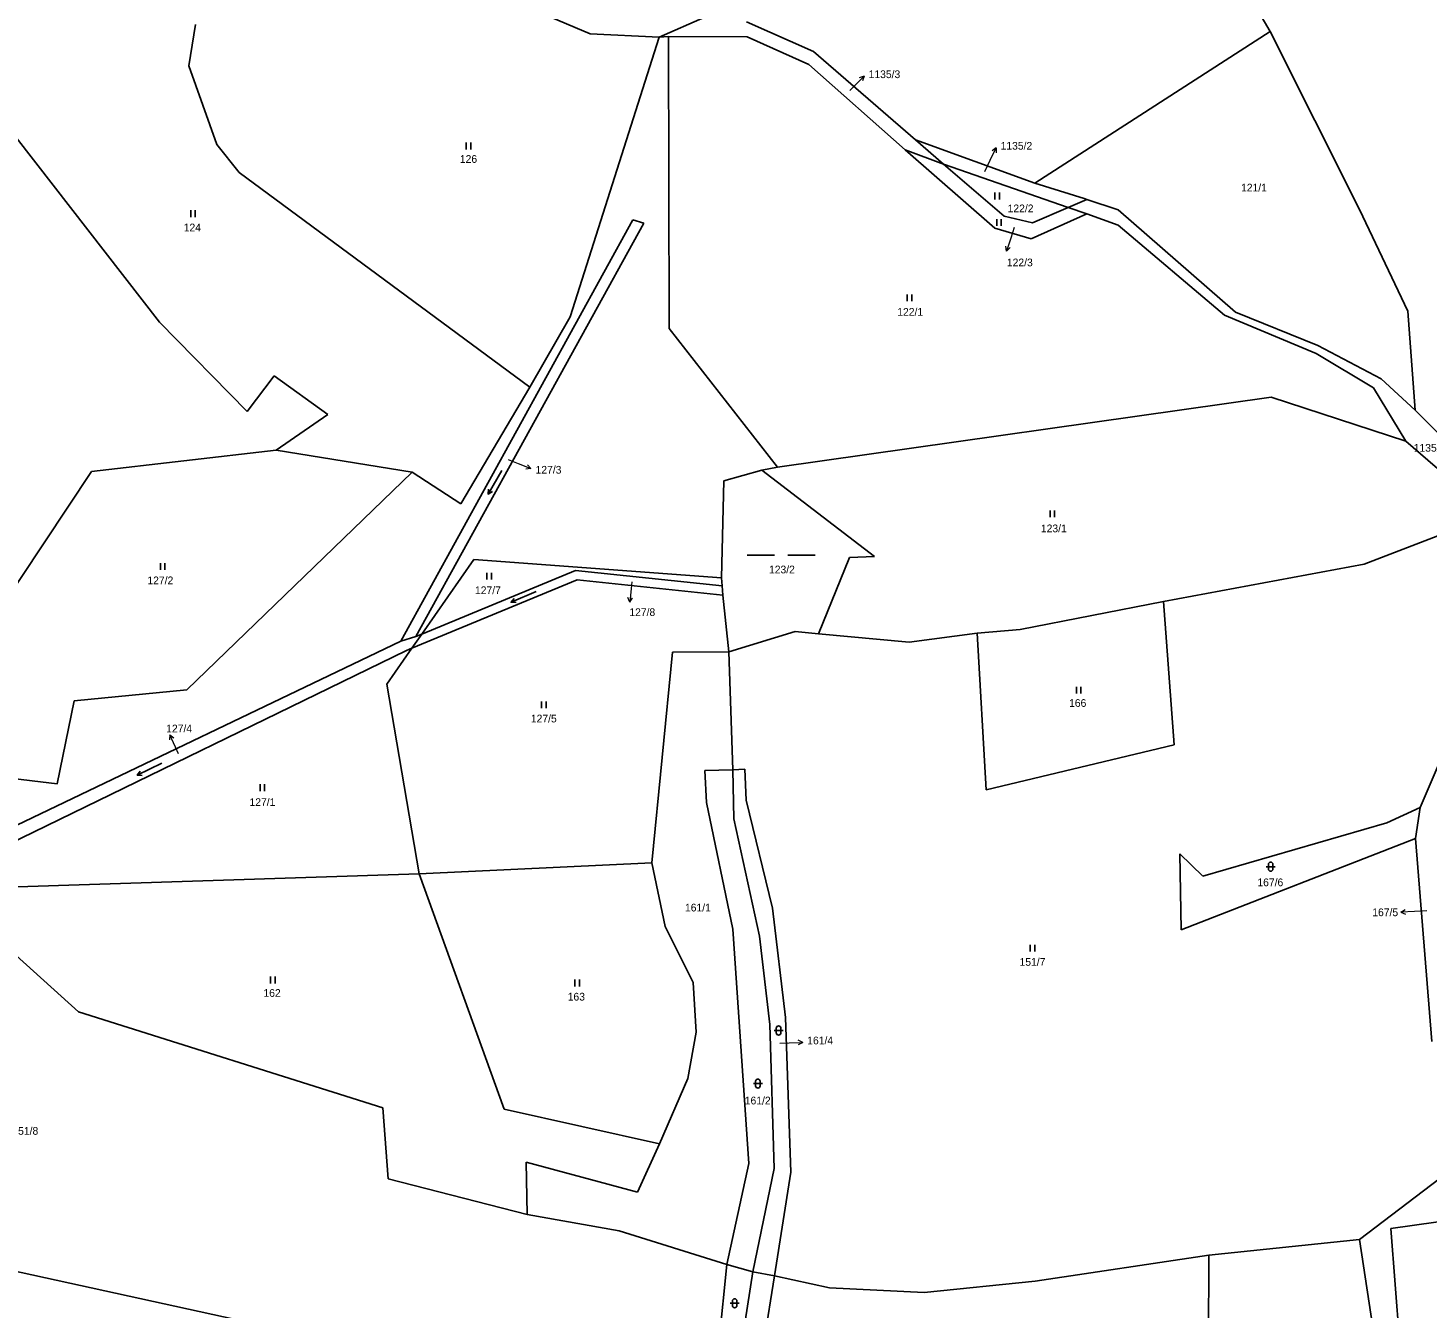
# Model space of a CAD drawing. Extents: x -765428 to -762163, y -1107632 to -1104975.
# Drawn here: x -763576.9 to -763268.9, y -1106368.4 to -1106086.6 of the extents above; entities that cross this region are included whole.
import ezdxf
from ezdxf.enums import TextEntityAlignment as Align

# ---------------------------------------------------------------- set-up
doc = ezdxf.new("R2010")
doc.units = 0
doc.header["$LTSCALE"] = 0.68
for name, color, linetype, lineweight in [('1', 7, 'Continuous', 25), ('3', 7, 'Continuous', 25), ('7', 7, 'Continuous', 13)]:
    doc.layers.add(name, color=color, linetype=linetype, lineweight=lineweight)
doc.layers.add('2', color=7, linetype='Continuous')

msp = doc.modelspace()

# ---------------------------------------------------------------- linework, layer by layer
at = {"layer": '1'}
for p, q in [((-763329.35, -1106043.44), (-763303.61, -1106087.39)), ((-763453.2, -1106087.94), (-763472.16, -1106079.89)), ((-763541.52, -1106094.99), (-763540.04, -1106085.9)), ((-763428.02, -1106084.29), (-763438.04, -1106088.64)), ((-763404.09, -1106091.81), (-763418.79, -1106085.26)), ((-763457.64, -1106150.19), (-763438.04, -1106088.64)), ((-763438.04, -1106088.64), (-763453.2, -1106087.94)), ((-763435.94, -1106088.55), (-763438.04, -1106088.64)), ((-763435.8, -1106152.77), (-763435.94, -1106088.55)), ((-763418.65, -1106088.59), (-763435.94, -1106088.55)), ((-763405.1, -1106094.66), (-763418.65, -1106088.59)), ((-763303.61, -1106087.39), (-763355.41, -1106120.75)), ((-763303.61, -1106087.39), (-763284, -1106126.56)), ((-763381.62, -1106111.27), (-763404.09, -1106091.81)), ((-763535.34, -1106112.24), (-763541.52, -1106094.99)), ((-763383.95, -1106113.42), (-763405.1, -1106094.66)), ((-763583.36, -1106105.79), (-763547.96, -1106151.37)), ((-763381.62, -1106111.27), (-763375.48, -1106116.58)), ((-763355.41, -1106120.75), (-763381.62, -1106111.27)), ((-763530.4, -1106118.46), (-763535.34, -1106112.24)), ((-763375.48, -1106116.58), (-763383.95, -1106113.42)), ((-763383.95, -1106113.42), (-763364.21, -1106130.66)), ((-763375.48, -1106116.58), (-763362.16, -1106128)), ((-763348.04, -1106126.1), (-763375.48, -1106116.58)), ((-763466.45, -1106165.63), (-763530.4, -1106118.46)), ((-763344.52, -1106124.15), (-763355.41, -1106120.75)), ((-763355.89, -1106129.48), (-763348.04, -1106126.1)), ((-763348.04, -1106126.1), (-763343.95, -1106124.34)), ((-763343.96, -1106127.52), (-763348.04, -1106126.1)), ((-763343.95, -1106124.34), (-763344.52, -1106124.15)), ((-763337.08, -1106126.66), (-763343.95, -1106124.34)), ((-763311.25, -1106149.14), (-763337.08, -1106126.66)), ((-763284, -1106126.56), (-763273.31, -1106148.94)), ((-763443.8, -1106128.85), (-763494.88, -1106221.53)), ((-763441.41, -1106129.57), (-763491.52, -1106220.5)), ((-763443.8, -1106128.85), (-763441.41, -1106129.57)), ((-763362.16, -1106128), (-763355.89, -1106129.48)), ((-763356.22, -1106132.99), (-763343.96, -1106127.52)), ((-763337.06, -1106130), (-763343.96, -1106127.52)), ((-763313.65, -1106149.79), (-763337.06, -1106130)), ((-763364.21, -1106130.66), (-763356.22, -1106132.99)), ((-763547.96, -1106151.37), (-763528.69, -1106170.98)), ((-763466.45, -1106165.63), (-763457.64, -1106150.19)), ((-763293.51, -1106158.23), (-763313.65, -1106149.79)), ((-763293.11, -1106156.45), (-763311.25, -1106149.14)), ((-763273.31, -1106148.94), (-763271.76, -1106170.68)), ((-763435.8, -1106152.77), (-763412.03, -1106183.24)), ((-763279.18, -1106163.78), (-763293.11, -1106156.45)), ((-763280.88, -1106165.81), (-763293.51, -1106158.23)), ((-763528.69, -1106170.98), (-763522.7, -1106163.17)), ((-763522.7, -1106163.17), (-763510.94, -1106171.64)), ((-763271.76, -1106170.68), (-763279.18, -1106163.78)), ((-763481.66, -1106191.32), (-763466.45, -1106165.63)), ((-763273.81, -1106177.51), (-763280.88, -1106165.81)), ((-763303.4, -1106167.85), (-763412.03, -1106183.24)), ((-763273.81, -1106177.51), (-763303.4, -1106167.85)), ((-763510.94, -1106171.64), (-763522.29, -1106179.5)), ((-763257.11, -1106185.37), (-763271.76, -1106170.68)), ((-763255.03, -1106193.78), (-763273.81, -1106177.51)), ((-763522.29, -1106179.5), (-763562.87, -1106184.23)), ((-763522.29, -1106179.5), (-763492.36, -1106184.33)), ((-763562.87, -1106184.23), (-763591.84, -1106227.65)), ((-763541.93, -1106232.24), (-763492.36, -1106184.33)), ((-763492.36, -1106184.33), (-763481.66, -1106191.32)), ((-763415.47, -1106183.87), (-763423.77, -1106186.22)), ((-763412.03, -1106183.24), (-763415.47, -1106183.87)), ((-763390.67, -1106202.88), (-763415.47, -1106183.87)), ((-763423.77, -1106186.22), (-763424.35, -1106207.55)), ((-763282.95, -1106204.58), (-763256.59, -1106194.39)), ((-763490.23, -1106219.97), (-763478.79, -1106203.58)), ((-763478.79, -1106203.58), (-763424.35, -1106207.55)), ((-763396.19, -1106203.09), (-763402.95, -1106219.87)), ((-763390.67, -1106202.88), (-763396.19, -1106203.09)), ((-763456.42, -1106205.99), (-763490.23, -1106219.97)), ((-763456.42, -1106205.99), (-763424.17, -1106209.36)), ((-763327.09, -1106212.77), (-763282.95, -1106204.58)), ((-763456.05, -1106208.06), (-763492.41, -1106223.08)), ((-763456.05, -1106208.06), (-763424, -1106211.41)), ((-763424.35, -1106207.55), (-763424.17, -1106209.36)), ((-763424.17, -1106209.36), (-763424, -1106211.41)), ((-763424, -1106211.41), (-763422.67, -1106223.88)), ((-763358.6, -1106218.92), (-763327.09, -1106212.77)), ((-763324.71, -1106244.32), (-763327.09, -1106212.77)), ((-763408.12, -1106219.4), (-763422.67, -1106223.88)), ((-763402.95, -1106219.87), (-763408.12, -1106219.4)), ((-763368.08, -1106219.78), (-763358.6, -1106218.92)), ((-763494.88, -1106221.53), (-763581.17, -1106262.89)), ((-763491.52, -1106220.5), (-763494.88, -1106221.53)), ((-763492.41, -1106223.08), (-763490.23, -1106219.97)), ((-763490.23, -1106219.97), (-763491.52, -1106220.5)), ((-763402.95, -1106219.87), (-763383.06, -1106221.73)), ((-763383.06, -1106221.73), (-763368.08, -1106219.78)), ((-763368.08, -1106219.78), (-763366.08, -1106254.19)), ((-763493.63, -1106223.59), (-763581.23, -1106266.21)), ((-763497.9, -1106230.95), (-763492.41, -1106223.08)), ((-763492.41, -1106223.08), (-763493.63, -1106223.59)), ((-763439.61, -1106270.25), (-763435.09, -1106223.93)), ((-763435.09, -1106223.93), (-763422.67, -1106223.88)), ((-763421.84, -1106249.8), (-763422.67, -1106223.88)), ((-763490.85, -1106272.72), (-763497.9, -1106230.95)), ((-763566.7, -1106234.64), (-763541.93, -1106232.24)), ((-763366.08, -1106254.19), (-763324.71, -1106244.32)), ((-763427.96, -1106249.98), (-763421.84, -1106249.8)), ((-763427.64, -1106256.97), (-763427.96, -1106249.98)), ((-763421.84, -1106249.8), (-763419.19, -1106249.66)), ((-763421.84, -1106249.8), (-763421.57, -1106260.61)), ((-763419.19, -1106249.66), (-763418.86, -1106256.49)), ((-763270.65, -1106258.08), (-763265.98, -1106247.33)), ((-763421.84, -1106284.89), (-763427.64, -1106256.97)), ((-763418.86, -1106256.49), (-763413.11, -1106280.26)), ((-763277.95, -1106261.45), (-763270.65, -1106258.08)), ((-763270.65, -1106258.08), (-763271.65, -1106264.9)), ((-763421.57, -1106260.61), (-763415.98, -1106286.39)), ((-763318.47, -1106273.2), (-763277.95, -1106261.45)), ((-763323.22, -1106285.03), (-763271.65, -1106264.9)), ((-763271.65, -1106264.9), (-763268.06, -1106309.55)), ((-763323.47, -1106268.29), (-763318.47, -1106273.2)), ((-763323.47, -1106268.29), (-763323.22, -1106285.03)), ((-763490.85, -1106272.72), (-763439.61, -1106270.25)), ((-763436.68, -1106284.24), (-763439.61, -1106270.25)), ((-763599.23, -1106276.16), (-763490.85, -1106272.72)), ((-763490.85, -1106272.72), (-763472.1, -1106324.42)), ((-763413.11, -1106280.26), (-763410.26, -1106304.3)), ((-763430.55, -1106296.62), (-763436.68, -1106284.24)), ((-763418.28, -1106336.44), (-763421.84, -1106284.89)), ((-763415.98, -1106286.39), (-763413.7, -1106305.8)), ((-763565.74, -1106303.01), (-763579.48, -1106290.69)), ((-763429.89, -1106307.5), (-763430.55, -1106296.62)), ((-763498.83, -1106324.16), (-763565.74, -1106303.01)), ((-763410.26, -1106304.3), (-763409.07, -1106338.32)), ((-763431.74, -1106317.74), (-763429.89, -1106307.5)), ((-763413.7, -1106305.8), (-763412.73, -1106337.54)), ((-763437.94, -1106332.06), (-763431.74, -1106317.74)), ((-763497.64, -1106339.78), (-763498.83, -1106324.16)), ((-763472.1, -1106324.42), (-763437.94, -1106332.06)), ((-763442.76, -1106342.69), (-763437.94, -1106332.06)), ((-763467.25, -1106336.14), (-763442.76, -1106342.69)), ((-763467.25, -1106336.14), (-763467.04, -1106347.59)), ((-763423.16, -1106358.59), (-763418.28, -1106336.44)), ((-763412.73, -1106337.54), (-763417.41, -1106360.22)), ((-763409.07, -1106338.32), (-763412.69, -1106361.14)), ((-763262.82, -1106337.09), (-763283.96, -1106353.12)), ((-763467.04, -1106347.59), (-763497.64, -1106339.78)), ((-763467.04, -1106347.59), (-763446.83, -1106351.23)), ((-763251.8, -1106347.17), (-763277.09, -1106350.73)), ((-763618.27, -1106351.7), (-763461.07, -1106385.99)), ((-763446.83, -1106351.23), (-763423.16, -1106358.59)), ((-763277.09, -1106350.73), (-763273.44, -1106397.91)), ((-763283.96, -1106353.12), (-763317.15, -1106356.55)), ((-763283.96, -1106353.12), (-763277.16, -1106397.91)), ((-763355.33, -1106362.27), (-763317.15, -1106356.55)), ((-763317.15, -1106356.55), (-763317.25, -1106398.34)), ((-763427.18, -1106398.62), (-763423.16, -1106358.59)), ((-763417.41, -1106360.22), (-763423.99, -1106401.96)), ((-763417.41, -1106360.22), (-763423.16, -1106358.59)), ((-763412.69, -1106361.14), (-763419.03, -1106401.1)), ((-763417.41, -1106360.22), (-763412.69, -1106361.14)), ((-763412.69, -1106361.14), (-763400.59, -1106363.72)), ((-763400.59, -1106363.72), (-763379.74, -1106364.79)), ((-763379.74, -1106364.79), (-763355.33, -1106362.27))]:
    msp.add_line(p, q, dxfattribs=at)
msp.add_lwpolyline([(-763593.73, -1106250.12), (-763570.42, -1106252.88), (-763566.7, -1106234.64)], dxfattribs=at)
at = {"layer": '3'}
for p, q in [((-763480.491, -1106113.34), (-763480.491, -1106111.84)), ((-763479.49, -1106113.34), (-763479.49, -1106111.84)), ((-763364.201, -1106124.36), (-763364.201, -1106122.86)), ((-763363.2, -1106124.36), (-763363.2, -1106122.86)), ((-763541.071, -1106128.23), (-763541.071, -1106126.73)), ((-763540.07, -1106128.23), (-763540.07, -1106126.73)), ((-763363.781, -1106130.18), (-763363.781, -1106128.68)), ((-763362.78, -1106130.18), (-763362.78, -1106128.68)), ((-763383.461, -1106146.75), (-763383.461, -1106145.25)), ((-763382.46, -1106146.75), (-763382.46, -1106145.25)), ((-763475.646, -1106189.159), (-763475.592, -1106188.062)), ((-763352.041, -1106194.24), (-763352.041, -1106192.74)), ((-763351.04, -1106194.24), (-763351.04, -1106192.74)), ((-763418.689, -1106202.63), (-763412.689, -1106202.63)), ((-763409.689, -1106202.63), (-763403.689, -1106202.63)), ((-763547.751, -1106205.85), (-763547.751, -1106204.35)), ((-763546.75, -1106205.85), (-763546.75, -1106204.35)), ((-763475.911, -1106207.95), (-763475.911, -1106206.45)), ((-763474.91, -1106207.95), (-763474.91, -1106206.45)), ((-763470.601, -1106212.941), (-763469.897, -1106212.098)), ((-763346.261, -1106233.05), (-763346.261, -1106231.55)), ((-763345.26, -1106233.05), (-763345.26, -1106231.55)), ((-763463.921, -1106236.26), (-763463.921, -1106234.76)), ((-763462.92, -1106236.26), (-763462.92, -1106234.76)), ((-763552.856, -1106251.005), (-763552.197, -1106250.126)), ((-763525.811, -1106254.5), (-763525.811, -1106253)), ((-763524.81, -1106254.5), (-763524.81, -1106253)), ((-763304.511, -1106271.121), (-763302.509, -1106271.121)), ((-763304.011, -1106270.621), (-763304.011, -1106271.622)), ((-763303.009, -1106271.622), (-763303.009, -1106270.621)), ((-763356.421, -1106289.79), (-763356.421, -1106288.29)), ((-763355.42, -1106289.79), (-763355.42, -1106288.29)), ((-763523.521, -1106296.8), (-763523.521, -1106295.3)), ((-763522.52, -1106296.8), (-763522.52, -1106295.3)), ((-763456.591, -1106297.44), (-763456.591, -1106295.94)), ((-763455.59, -1106297.44), (-763455.59, -1106295.94)), ((-763412.761, -1106307.151), (-763410.759, -1106307.151)), ((-763412.261, -1106306.651), (-763412.261, -1106307.652)), ((-763411.259, -1106307.652), (-763411.259, -1106306.651)), ((-763417.311, -1106318.831), (-763415.309, -1106318.831)), ((-763416.811, -1106318.331), (-763416.811, -1106319.332)), ((-763415.809, -1106319.332), (-763415.809, -1106318.331)), ((-763422.431, -1106367.141), (-763420.429, -1106367.141)), ((-763421.931, -1106366.641), (-763421.931, -1106367.642)), ((-763420.929, -1106367.642), (-763420.929, -1106366.641))]:
    msp.add_line(p, q, dxfattribs=at)
for points in [[(-763472.646, -1106183.962), (-763475.646, -1106189.159), (-763474.723, -1106188.563)], [(-763465.078, -1106210.597), (-763470.601, -1106212.941), (-763469.505, -1106213.021)], [(-763547.463, -1106248.375), (-763552.856, -1106251.005), (-763551.757, -1106251.027)]]:
    msp.add_lwpolyline(points, dxfattribs=at)
for centre, start, end in [((-763303.51, -1106270.6209), 0, 180), ((-763303.51, -1106271.6209), 180, 359.98789), ((-763411.76, -1106306.6509), 0, 180), ((-763411.76, -1106307.6509), 180, 359.98789), ((-763416.31, -1106318.3309), 0, 180), ((-763416.31, -1106319.3309), 180, 359.98789), ((-763421.43, -1106366.6409), 0, 180), ((-763421.43, -1106367.6409), 180, 359.98789)]:
    msp.add_arc(centre, 0.5, start, end, dxfattribs=at)
at = {"layer": '7'}
for p, q in [((-763392.948, -1106097.238), (-763394.01, -1106097.592)), ((-763363.932, -1106112.97), (-763364.809, -1106113.666)), ((-763361.597, -1106135.714), (-763360.812, -1106134.916)), ((-763466.248, -1106183.564), (-763466.988, -1106182.725)), ((-763444.504, -1106212.935), (-763443.901, -1106211.991)), ((-763545.688, -1106242.09), (-763545.719, -1106243.209)), ((-763274.907, -1106281.117), (-763273.881, -1106281.565)), ((-763406.461, -1106309.755), (-763407.479, -1106309.29))]:
    msp.add_line(p, q, dxfattribs=at)
for points in [[(-763396.1, -1106100.38), (-763395.07, -1106099.36), (-763392.948, -1106097.238), (-763393.302, -1106098.3)], [(-763366.39, -1106118.21), (-763365.2, -1106115.69), (-763363.932, -1106112.97), (-763363.901, -1106114.089)], [(-763359.91, -1106130.55), (-763360.67, -1106132.86), (-763361.597, -1106135.714), (-763361.764, -1106134.607)], [(-763471.25, -1106181.53), (-763469.03, -1106182.44), (-763466.248, -1106183.564), (-763467.364, -1106183.653)], [(-763444.04, -1106208.46), (-763444.19, -1106209.95), (-763444.504, -1106212.935), (-763444.897, -1106211.886)], [(-763543.74, -1106246.29), (-763544.42, -1106244.81), (-763545.688, -1106242.09), (-763544.811, -1106242.786)], [(-763269.15, -1106280.81), (-763271.91, -1106280.96), (-763274.907, -1106281.117), (-763273.933, -1106280.565)], [(-763411.52, -1106309.92), (-763409.46, -1106309.86), (-763406.461, -1106309.755), (-763407.444, -1106310.291)]]:
    msp.add_lwpolyline(points, dxfattribs=at)

# ---------------------------------------------------------------- texts
at = {"layer": '2'}
for s, p in [('1135/3', (-763391.95, -1106097.665)), ('1135/2', (-763362.92, -1106113.405)), ('126', (-763481.87, -1106116.305)), ('121/1', (-763310.03, -1106122.605)), ('127/3', (-763465.22, -1106184.665)), ('123/1', (-763354.06, -1106197.565)), ('123/2', (-763413.87, -1106206.605)), ('167/6', (-763306.43, -1106275.415)), ('161/1', (-763432.35, -1106280.965)), ('161/4', (-763405.46, -1106310.195))]:
    msp.add_text(s, height=1.7, dxfattribs=at).set_placement(p)
for s, p in [('122/2', (-763358.53, -1106127.175)), ('124', (-763540.719, -1106131.375)), ('122/1', (-763382.81, -1106149.945)), ('1135/1', (-763268.57, -1106179.835)), ('127/2', (-763547.76, -1106208.995)), ('127/7', (-763475.7, -1106211.175)), ('166', (-763345.959, -1106235.965)), ('127/5', (-763463.41, -1106239.385)), ('127/1', (-763525.3, -1106257.765)), ('151/7', (-763355.91, -1106292.915)), ('162', (-763523.179, -1106299.745)), ('163', (-763456.249, -1106300.565)), ('161/2', (-763416.35, -1106323.405)), ('151/8', (-763577.46, -1106330.085))]:
    msp.add_text(s, height=1.7, dxfattribs=at).set_placement(p, align=Align.CENTER)
for s, p in [('122/3', (-763355.85, -1106139.065)), ('127/8', (-763438.9, -1106215.985)), ('127/4', (-763540.78, -1106241.575)), ('167/5', (-763275.47, -1106282.005))]:
    msp.add_text(s, height=1.7, dxfattribs=at).set_placement(p, align=Align.RIGHT)

doc.saveas('drawing.dxf')
